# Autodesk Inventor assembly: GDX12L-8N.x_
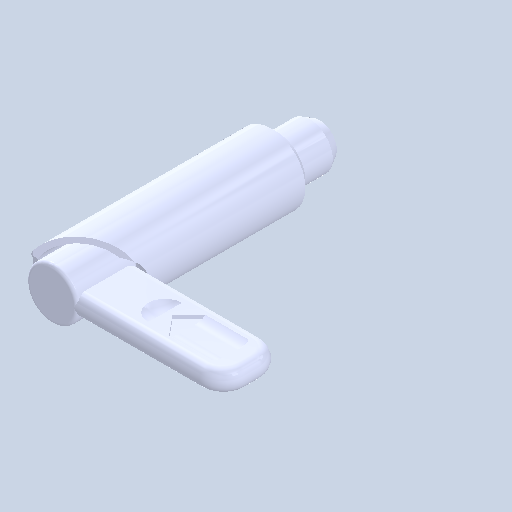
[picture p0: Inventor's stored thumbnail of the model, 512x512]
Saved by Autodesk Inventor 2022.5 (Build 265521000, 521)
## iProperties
Created: 2024-06
Part Number: GDX12L-8N.x_
Document SubType Name: Assembly
Designer: ImaoCorp
Author: ImaoCorp
Sending System: SOLIDWORKS 2022-2022290
MC: AMD64
MC_MODEL: Intel64 Family 6 Model 60 Stepping 3, GenuineIntel
OS: Windows_NT
FRU: Parasolid Version 33.1, build 260,  4-25-2022
FORMAT: text
GUISE: transmit
KEY: FILEGDX12L-8N.x_t
DATE: Wed Jun 12 09:31:50 2024
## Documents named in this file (3)
- Y:\5.更新分\2024年対応\xxxx_GDX\データ_imao品番\gdx12l-8n\GDX12L-8N.x_.iam
- Y:\5.更新分\2024年対応\xxxx_GDX\データ_imao品番\gdx12l-8n\GDX12L-8N_01.ipt
- Y:\5.更新分\2024年対応\xxxx_GDX\データ_imao品番\gdx12l-8n\GDX12L-8N_02.ipt
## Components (2 placed, 2 different names)
1. GDX12L-8N_01
2. GDX12L-8N_02
